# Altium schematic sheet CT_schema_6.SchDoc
size 367 x 243 mm
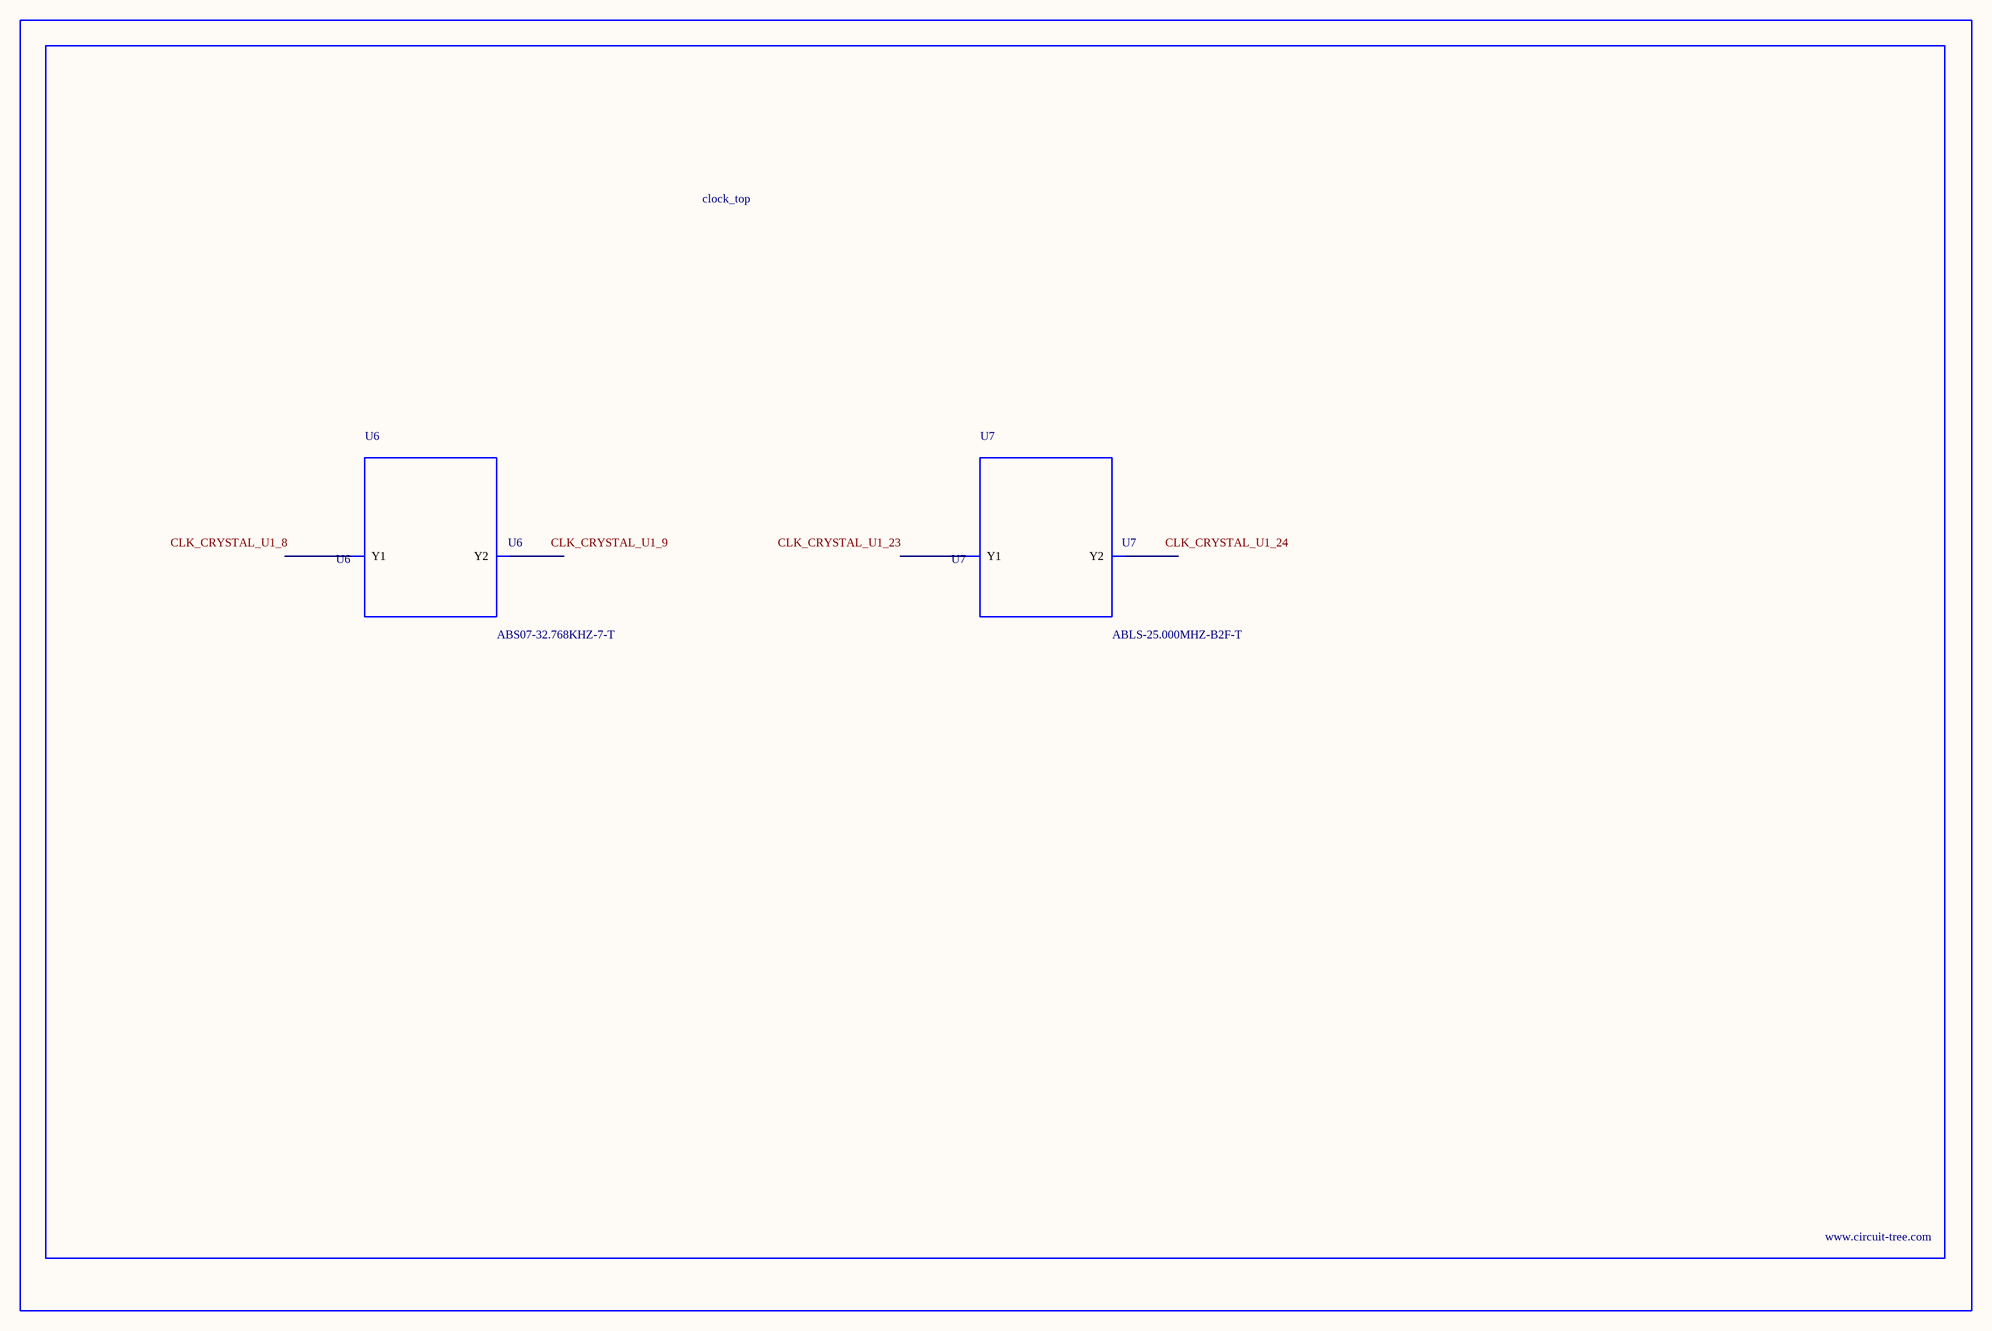
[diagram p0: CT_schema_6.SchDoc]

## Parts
BORDER5  (no value)
U6  ABS07-32.768KHZ-7-T  [ABS07-32.768KHZ-7-T]
U7  ABLS-25.000MHZ-B2F-T  [ABLS-25.000MHZ-B2F-T]

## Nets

Not connected (* = marked no-connect by the designer): U6 1(Y1) 2(Y2); U7 1(Y1) 2(Y2)

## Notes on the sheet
- Labels drawn without touching a wire or pin: CLK_CRYSTAL_U1_8, CLK_CRYSTAL_U1_9, CLK_CRYSTAL_U1_23, CLK_CRYSTAL_U1_24

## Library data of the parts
BORDER5 = BORDER_PAGE5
